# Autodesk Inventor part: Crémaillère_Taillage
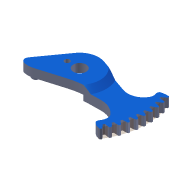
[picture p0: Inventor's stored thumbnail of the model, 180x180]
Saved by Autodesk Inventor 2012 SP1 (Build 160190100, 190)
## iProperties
Created: 2014-12
Part Number: Crémaillère_Taillage
Material: Default
Document SubType Name: Modeling
Designer: Bruno
Density: 1 g/cm^3
Mass: 8.41821 g
Surface Area: 46.446 cm^2
Volume: 8.41821 cm^3
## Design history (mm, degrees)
node "Crémaillère_Taillage1"
sketch "Esquisse3"
  geometry: C1 r 6.75 at (52.405, -4.519) reference; A1 r 14.635 centre (42.992, 2.923) between (43.877, 17.531) and (38.203, 16.752) reference; A2 r 14.635 centre (41.649, -11.053) between (36.679, -24.818) and (39.738, -25.563) reference; A3 r 43.86 centre (0, 0) between (41.882, 13.022) and (41.494, 14.209) reference; A4 r 45.85 centre (0, 0) between (38.246, -25.287) and (42.361, 17.544)
  constraints: 4 point on circle, 1 centre point, 1 coincident, 1 tangent
feature "SrfExtrusion2" sketch "Esquisse3" dims "d3" = 6, "d4" = 0
node "Crémaillère_Taillage"
node "Base1"
node "Référence3"
body "Srf2"
